RoboDK station: Skid_frame_side_2P_2R_edwelds.rdk

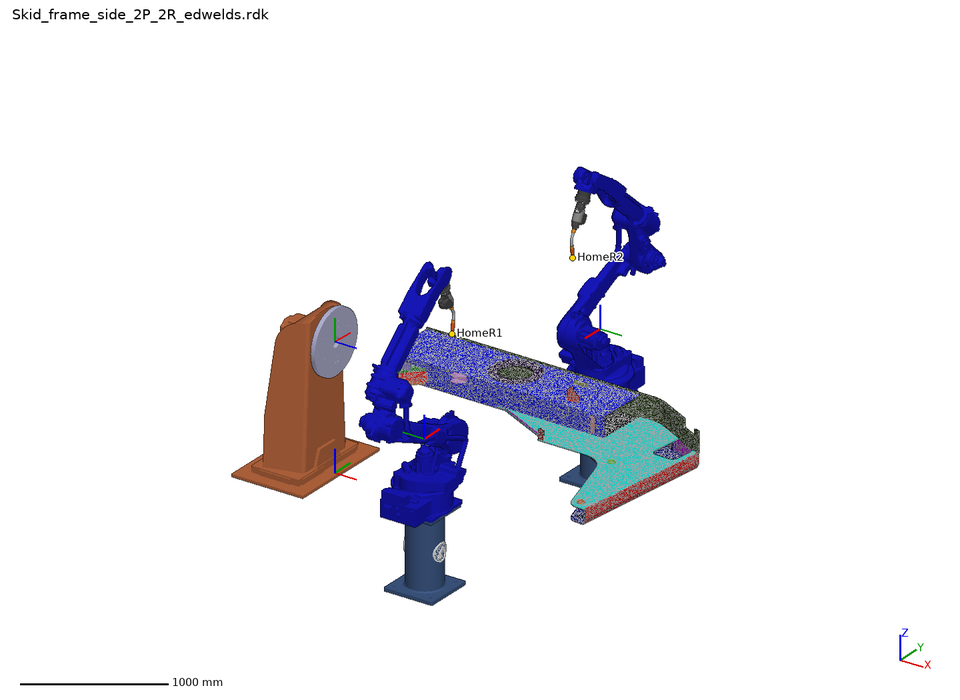
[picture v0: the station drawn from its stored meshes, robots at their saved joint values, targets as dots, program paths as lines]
Station New Station (1) (saved by RoboDK 5.7.4). Poses are relative to the parent item; angles as X-Y-Z fixed-axis rotations.
  - frame Motoman AR2010 Base-1 at (1500, 910, 1110) mm, rotated rx 0 ry 0 rz 90 deg
    - robot Motoman AR2010-1 (model Motoman AR2010): 6 axes
        modified DH rows (alpha deg, a mm, theta deg, d mm): 0, 0, 0, 505; -90, 150, -90, 0; 0, 760, 0, 0; -90, 200, 0, 1082; 90, 0, 0, 0; -90, 0, 0, 100
        base shift (0, 0, -505) mm
        joint limits [-180, -105, -86, -150, -135, -210] to [180, 155, 160, 150, 90, 210]; home [0, 0, 0, 0, 0, 0]; saved at [0, -65.2, -23.68, 0, -103.5, -180]
      - tool Fronius MTB500i Welding Gun-1, TCP at (86, 0, 451.5) mm, rotated rx 0 ry 36 rz 0 deg, size 139 x 105 x 455.9 mm
    - target HomeR1 (Cartesian target) at (320.8, 0, 658.51) mm, rotated rx 180 ry -7.98 rz -180 deg; joints [0, -65.2, -23.68, 0, -103.5, -180] of Motoman AR2010-1
    - object Pedestal H24in (Type 1) at (0, 0, -1115) mm, size 400 x 400 x 609.6 mm, geometry from Pedestal-H24in-Type-1.sld
  - frame Motoman AR2010 Base-2 at (1500, 2970, 1110) mm, rotated rx 0 ry 0 rz -90 deg
    - robot Motoman AR2010-2 (model Motoman AR2010): 6 axes
        modified DH rows (alpha deg, a mm, theta deg, d mm): 0, 0, 0, 505; -90, 150, -90, 0; 0, 760, 0, 0; -90, 200, 0, 1082; 90, 0, 0, 0; -90, 0, 0, 100
        base shift (0, 0, -505) mm
        joint limits [-180, -105, -86, -150, -135, -210] to [180, 155, 160, 150, 90, 210]; home [0, 0, 0, 0, 0, 0]; saved at [0, -65.2, -23.68, 0, -103.5, -180]
      - tool Fronius MTB500i Welding Gun-2, TCP at (86, 0, 451.5) mm, rotated rx 0 ry 36 rz 0 deg, size 139 x 105 x 455.9 mm
    - target HomeR2 (Cartesian target) at (320.8, 0, 658.51) mm, rotated rx 180 ry -7.98 rz -180 deg; joints [0, -65.2, -23.68, 0, -103.5, -180] of Motoman AR2010-2
    - object Pedestal H24in (Type 1) at (0, 0, -1115) mm, size 400 x 400 x 609.6 mm, geometry from Pedestal-H24in-Type-1.sld
  - frame KUKA KP1 H1000 EH980 Base at (0, 2000, 0) mm
    - robot KUKA KP1 H1000 EH980: 1 axes, payload 1000 kg
        modified DH rows (alpha deg, a mm, theta deg, d mm): 0, 0, 0, 0
        base shift (0, 0, 980) mm, rotated rx 0 ry 90 rz 0 deg
        joint limits [-190] to [190]; home [0]; saved at [89]
      - frame Frame 3 at (0, 0, 0) mm
        - object Grabcad_Skid_frame_side_step at (220, 0, 600) mm, rotated rx 0 ry -90 rz 0 deg, size 2411.7 x 367 x 1430.7 mm, geometry from Grabcad_Skid_frame_side_step.stp
    - target P1 (Cartesian target) at (0, 0, 980) mm, rotated rx 90 ry 0 rz 90 deg; joints [90] of KUKA KP1 H1000 EH980
    - target P2 (Cartesian target) at (0, 0, 980) mm, rotated rx -90 ry 0 rz -90 deg; joints [-90] of KUKA KP1 H1000 EH980
